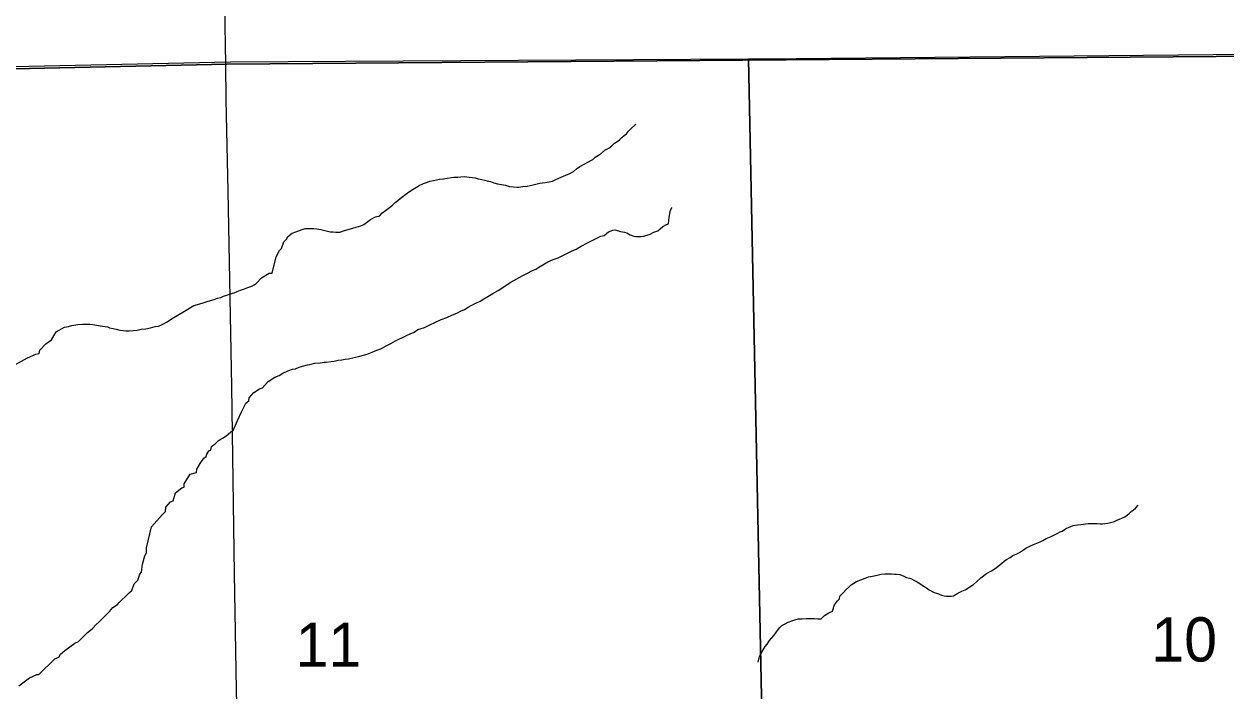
# Model space of a CAD drawing. Extents: x 10.6 to 44.6, y -2.6 to 23.4.
# Drawn here: x 17.431 to 18.57, y 20.326 to 20.958 of the extents above; entities that cross this region are included whole.
import ezdxf

# ---------------------------------------------------------------- set-up
doc = ezdxf.new("R2010")
doc.units = 0
for name, color, linetype in [('GM_X_Minor_River', 7, 'Continuous'), ('GM_X_Section', 7, 'Continuous'), ('GM_X_Section_Text', 7, 'Continuous'), ('GM_X_State_Route', 7, 'Continuous'), ('GM_X_Township', 7, 'Continuous')]:
    doc.layers.add(name, color=color, linetype=linetype)

msp = doc.modelspace()

# ---------------------------------------------------------------- linework, layer by layer
at = {"layer": 'GM_X_Minor_River'}
for points in [[(17.8942, 20.8036), (17.8976, 20.8032), (17.8995, 20.8033), (17.9033, 20.8038), (17.9075, 20.8042), (17.9132, 20.8055), (17.9196, 20.8068), (17.9245, 20.8076), (17.9283, 20.8081), (17.9314, 20.8089), (17.9347, 20.8105), (17.9396, 20.8125), (17.9442, 20.8145), (17.9479, 20.8161), (17.9513, 20.8181), (17.9543, 20.8204), (17.9573, 20.8228), (17.9656, 20.8271), (17.9678, 20.8283), (17.9697, 20.8295), (17.972, 20.8315), (17.975, 20.8334), (17.978, 20.8354), (17.9809, 20.8381), (17.9847, 20.8401), (17.9877, 20.8424), (17.9903, 20.8448), (17.9933, 20.8467), (17.9952, 20.8483), (17.997, 20.8502), (17.9993, 20.8522), (18.0015, 20.8538), (18.0034, 20.8561), (18.0064, 20.8592), (18.0093, 20.8619), (18.0103, 20.8628)], [(17.5463, 20.6691), (17.5505, 20.6699), (17.555, 20.6712), (17.5581, 20.6716), (17.5603, 20.6724), (17.563, 20.6736), (17.5663, 20.6756), (17.5705, 20.6784), (17.5757, 20.6815), (17.5829, 20.6858), (17.5915, 20.691), (17.5994, 20.6934), (17.6043, 20.695), (17.6074, 20.6959), (17.6108, 20.6967), (17.6142, 20.6979), (17.6172, 20.6987), (17.6198, 20.6999), (17.6229, 20.7008), (17.6263, 20.702), (17.6297, 20.7032), (17.6327, 20.7044), (17.6357, 20.7056), (17.6395, 20.7068), (17.6429, 20.708), (17.6466, 20.7093), (17.6489, 20.7105), (17.6508, 20.712), (17.6556, 20.7174), (17.6631, 20.7218), (17.6658, 20.7218), (17.6696, 20.7371), (17.6729, 20.7433), (17.6748, 20.7452), (17.6769, 20.7513), (17.6799, 20.7541), (17.6803, 20.756), (17.6848, 20.7595), (17.6882, 20.7607), (17.6942, 20.7631), (17.6972, 20.7639), (17.7003, 20.764), (17.7025, 20.7641), (17.7052, 20.7641), (17.7079, 20.7638), (17.7102, 20.7635), (17.7121, 20.7631), (17.7144, 20.7624), (17.717, 20.7617), (17.7209, 20.761), (17.7235, 20.7607), (17.7262, 20.7604), (17.73, 20.7605), (17.7345, 20.7621), (17.7402, 20.7637), (17.7455, 20.7654), (17.7497, 20.7666), (17.7527, 20.7678), (17.7553, 20.7698), (17.759, 20.7725), (17.7636, 20.7749), (17.7677, 20.7761), (17.7699, 20.7784), (17.7733, 20.7812), (17.7771, 20.7839), (17.7797, 20.7862), (17.7823, 20.7886), (17.7849, 20.7905), (17.7871, 20.7925), (17.7939, 20.7976), (17.7988, 20.8011), (17.8025, 20.8031), (17.8051, 20.8047), (17.8093, 20.8067), (17.8131, 20.8079), (17.8153, 20.8087), (17.8187, 20.8095), (17.8214, 20.81), (17.8244, 20.8108), (17.8282, 20.8112), (17.8316, 20.8117), (17.8358, 20.8122), (17.8381, 20.8126), (17.8419, 20.8127), (17.8445, 20.8131), (17.8476, 20.8132), (17.8502, 20.8129), (17.8525, 20.8125), (17.8552, 20.8122), (17.8582, 20.8119), (17.8609, 20.8112), (17.8644, 20.8105), (17.8674, 20.8098), (17.8697, 20.8091), (17.8728, 20.8084), (17.8758, 20.8073), (17.8793, 20.8063), (17.8831, 20.8056), (17.8869, 20.8049), (17.8908, 20.8039), (17.8942, 20.8036)], [(17.8702, 20.6997), (17.875, 20.7024), (17.8799, 20.7052), (17.8852, 20.7087), (17.8912, 20.7127), (17.8976, 20.7162), (17.9032, 20.7194), (17.9077, 20.7218), (17.9119, 20.7238), (17.9156, 20.7254), (17.9186, 20.7273), (17.9224, 20.7297), (17.9269, 20.7324), (17.9322, 20.7345), (17.9367, 20.7361), (17.9405, 20.7381), (17.945, 20.7404), (17.9495, 20.7424), (17.954, 20.7444), (17.9585, 20.7472), (17.9646, 20.7504), (17.9774, 20.7567), (17.9804, 20.7575), (17.9845, 20.7607), (17.9886, 20.7623), (17.9909, 20.7627), (17.9959, 20.7613), (17.9997, 20.7606), (18.002, 20.7599), (18.0051, 20.7581), (18.0085, 20.7566), (18.0105, 20.7563), (18.0127, 20.7563), (18.015, 20.7564), (18.0177, 20.7568), (18.0211, 20.7577), (18.0241, 20.7585), (18.0275, 20.7605), (18.0313, 20.7617), (18.0335, 20.7636), (18.0361, 20.766), (18.0395, 20.7679), (18.0414, 20.7684), (18.042, 20.7748), (18.0434, 20.7813), (18.0445, 20.7836), (18.0445, 20.7836), (18.0445, 20.784)], [(17.5192, 20.4078), (17.521, 20.4098), (17.5236, 20.4125), (17.5266, 20.4152), (17.5307, 20.4191), (17.533, 20.421), (17.5351, 20.4275), (17.5385, 20.431), (17.5406, 20.4364), (17.5421, 20.4383), (17.5431, 20.446), (17.5452, 20.454), (17.5467, 20.4567), (17.5469, 20.4616), (17.5515, 20.4815), (17.5615, 20.4927), (17.5648, 20.4958), (17.5651, 20.5), (17.5696, 20.5051), (17.5722, 20.5059), (17.5744, 20.5135), (17.5803, 20.5182), (17.5826, 20.519), (17.5825, 20.5221), (17.5881, 20.5313), (17.5941, 20.5329), (17.5944, 20.536), (17.5977, 20.5414), (17.601, 20.5464), (17.6033, 20.548), (17.604, 20.5503), (17.6058, 20.5533), (17.6077, 20.5541), (17.6084, 20.5576), (17.6118, 20.5599), (17.6148, 20.5627), (17.6166, 20.5642), (17.6189, 20.5654), (17.6219, 20.5674), (17.6241, 20.5693), (17.6268, 20.5713), (17.629, 20.5725), (17.633, 20.582), (17.637, 20.5909), (17.641, 20.5986), (17.6436, 20.6009), (17.644, 20.6036), (17.6484, 20.6086), (17.6537, 20.6121), (17.6567, 20.613), (17.6619, 20.6192), (17.6683, 20.6231), (17.6724, 20.6247), (17.6758, 20.6271), (17.6807, 20.6291), (17.6852, 20.6307), (17.6879, 20.6311), (17.6913, 20.6327), (17.6947, 20.6335), (17.6992, 20.6348), (17.7015, 20.6352), (17.7064, 20.6365), (17.7113, 20.6369), (17.7151, 20.6374), (17.717, 20.6375), (17.7216, 20.6379), (17.7246, 20.6384), (17.7284, 20.6392), (17.7318, 20.6397), (17.7349, 20.6401), (17.7383, 20.6406), (17.7489, 20.6431), (17.7523, 20.6439), (17.7557, 20.6451), (17.7606, 20.6468), (17.7651, 20.6488), (17.7693, 20.6504), (17.7738, 20.6527), (17.7783, 20.6551), (17.7828, 20.6575), (17.7858, 20.6591), (17.7892, 20.6607), (17.793, 20.6627), (17.7967, 20.6643), (17.8005, 20.6659), (17.8039, 20.6682), (17.8103, 20.6703), (17.8152, 20.6726), (17.8205, 20.6754), (17.8261, 20.6778), (17.8314, 20.6798), (17.8367, 20.6822), (17.8408, 20.6838), (17.8442, 20.6858), (17.848, 20.6874), (17.8514, 20.6894), (17.8544, 20.691), (17.8589, 20.6933), (17.863, 20.6953), (17.8664, 20.6973), (17.8702, 20.6997)], [(17.4226, 20.6352), (17.4339, 20.6416), (17.4418, 20.6448), (17.4452, 20.6456), (17.4456, 20.6487), (17.4515, 20.6549), (17.4568, 20.6584), (17.4612, 20.6661), (17.4691, 20.6704), (17.4728, 20.6713), (17.4759, 20.6721), (17.4816, 20.673), (17.4861, 20.6735), (17.4884, 20.6735), (17.493, 20.6733), (17.4979, 20.6726), (17.5029, 20.6719), (17.5098, 20.671), (17.5117, 20.6699), (17.5151, 20.6692), (17.5182, 20.6685), (17.5216, 20.6678), (17.5247, 20.6675), (17.5273, 20.6672), (17.5304, 20.6672), (17.5342, 20.6673), (17.538, 20.6678), (17.5418, 20.6686), (17.5463, 20.6691)], [(18.4203, 20.4806), (18.4249, 20.4826), (18.429, 20.4834), (18.4321, 20.4835), (18.4347, 20.4839), (18.4366, 20.4843), (18.4389, 20.4844), (18.4419, 20.4845), (18.445, 20.4845), (18.4476, 20.4846), (18.4503, 20.4843), (18.4526, 20.4843), (18.4549, 20.4847), (18.4575, 20.4848), (18.464, 20.4864), (18.4662, 20.4876), (18.4688, 20.4888), (18.4715, 20.49), (18.4738, 20.4908), (18.476, 20.4924), (18.4779, 20.494), (18.4797, 20.4959), (18.4816, 20.4971), (18.4842, 20.4994), (18.4862, 20.502)], [(18.1263, 20.3533), (18.1277, 20.3587), (18.1288, 20.361), (18.1329, 20.3679), (18.1347, 20.3702), (18.1369, 20.3737), (18.1388, 20.376), (18.141, 20.3784), (18.1429, 20.3811), (18.1454, 20.3842), (18.1469, 20.3861), (18.1488, 20.388), (18.1518, 20.3896), (18.1548, 20.3912), (18.1582, 20.3924), (18.1612, 20.3932), (18.1643, 20.3941), (18.1681, 20.3942), (18.1719, 20.3946), (18.1749, 20.3947), (18.1779, 20.3944), (18.1798, 20.3944), (18.1829, 20.3941), (18.1859, 20.3942), (18.1893, 20.3973), (18.1934, 20.4), (18.1968, 20.4016), (18.1986, 20.4074), (18.2016, 20.4112), (18.2034, 20.4132), (18.2037, 20.4158), (18.2071, 20.4193), (18.2097, 20.422), (18.2127, 20.4248), (18.2145, 20.4263), (18.2168, 20.4279), (18.2194, 20.4295), (18.2277, 20.4327), (18.2307, 20.4339), (18.2345, 20.4347), (18.2391, 20.4356), (18.2429, 20.4364), (18.2463, 20.4369), (18.2505, 20.437), (18.2531, 20.437), (18.2554, 20.4367), (18.2573, 20.4367), (18.2604, 20.4361), (18.2642, 20.4346), (18.2669, 20.4335), (18.2696, 20.4328), (18.2715, 20.4321), (18.2738, 20.431), (18.2769, 20.4292), (18.2803, 20.427), (18.283, 20.4251), (18.2857, 20.4237), (18.2884, 20.4218), (18.2931, 20.4193), (18.2954, 20.4186), (18.2973, 20.4179), (18.3, 20.4168), (18.3026, 20.4161), (18.3045, 20.4157), (18.3072, 20.4158), (18.3091, 20.4158), (18.3114, 20.4159), (18.3155, 20.4186), (18.3193, 20.4206), (18.3223, 20.4218), (18.3302, 20.4269), (18.3332, 20.4293), (18.3373, 20.4332), (18.3425, 20.4371), (18.3474, 20.4398), (18.3508, 20.4418), (18.3534, 20.4438), (18.3553, 20.4453), (18.3571, 20.4469), (18.3594, 20.4488), (18.3616, 20.4504), (18.365, 20.4524), (18.3676, 20.4543), (18.3714, 20.4559), (18.374, 20.4571), (18.3767, 20.4591), (18.38, 20.4611), (18.3838, 20.463), (18.3872, 20.4646), (18.3902, 20.4658), (18.3929, 20.467), (18.3959, 20.4686), (18.3993, 20.4702), (18.4038, 20.4722), (18.4072, 20.4738), (18.4102, 20.4754), (18.4124, 20.4766), (18.4143, 20.4774), (18.4166, 20.479), (18.4184, 20.4801), (18.4203, 20.4806)], [(17.4257, 20.3309), (17.4358, 20.3384), (17.443, 20.3416), (17.4449, 20.3416), (17.4598, 20.3564), (17.4636, 20.358), (17.4654, 20.3607), (17.4695, 20.3642), (17.474, 20.3677), (17.4789, 20.3712), (17.4823, 20.3728), (17.4849, 20.3752), (17.4875, 20.3779), (17.4908, 20.3814), (17.4953, 20.3849), (17.499, 20.3888), (17.502, 20.3915), (17.505, 20.3946), (17.5084, 20.3977), (17.5117, 20.4012), (17.515, 20.4051), (17.5192, 20.4078)]]:
    msp.add_lwpolyline(points, dxfattribs=at)
at = {"layer": 'GM_X_Section'}
for points in [[(19.0401, 20.9394), (19.0693, 19.8492), (18.1394, 19.8405), (18.1171, 20.9247), (18.1295, 20.9248), (18.5902, 20.929), (19.0353, 20.9393)], [(18.1171, 20.9247), (18.1394, 19.8405), (17.1955, 19.8385), (17.1705, 20.912), (17.6263, 20.922)]]:
    msp.add_lwpolyline(points, close=True, dxfattribs=at)
at = {"layer": 'GM_X_State_Route'}
msp.add_lwpolyline([(17.6854, 19.0216), (17.6687, 19.1967), (17.6561, 19.3224), (17.6515, 19.3672), (17.6492, 19.3939), (17.6475, 19.4256), (17.6464, 19.4841), (17.6457, 19.5441), (17.6443, 19.6217), (17.6428, 19.728), (17.6411, 19.8286), (17.6406, 19.8566), (17.6372, 20.0434), (17.635, 20.1583), (17.6338, 20.2435), (17.6321, 20.3274), (17.6302, 20.4369), (17.6276, 20.6144), (17.6241, 20.7993), (17.6224, 20.8858), (17.6219, 20.9197), (17.6207, 20.9933)], dxfattribs=at)
at = {"layer": 'GM_X_Township'}
for points in [[(15.2363, 22.3267), (15.2375, 22.264), (15.2389, 21.9444), (15.2493, 21.2218), (15.2514, 21.0808), (15.2545, 20.8646), (16.6438, 20.8983), (17.623, 20.9197), (18.6416, 20.9277), (19.6581, 20.9527), (20.0033, 20.9573)], [(20.0033, 20.9573), (19.6581, 20.9527), (18.6416, 20.9277), (17.623, 20.9197), (16.6438, 20.8983), (15.2545, 20.8646), (15.2587, 20.5958), (15.2685, 20.051), (15.2709, 19.5646)]]:
    msp.add_lwpolyline(points, dxfattribs=at)

# ---------------------------------------------------------------- texts
at = {"layer": 'GM_X_Section_Text'}
for s, p in [('10', (18.4988, 20.3538)), ('11', (17.688, 20.3488))]:
    msp.add_text(s, height=0.04186, rotation=0, dxfattribs=at).set_placement(p)

doc.saveas('drawing.dxf')
